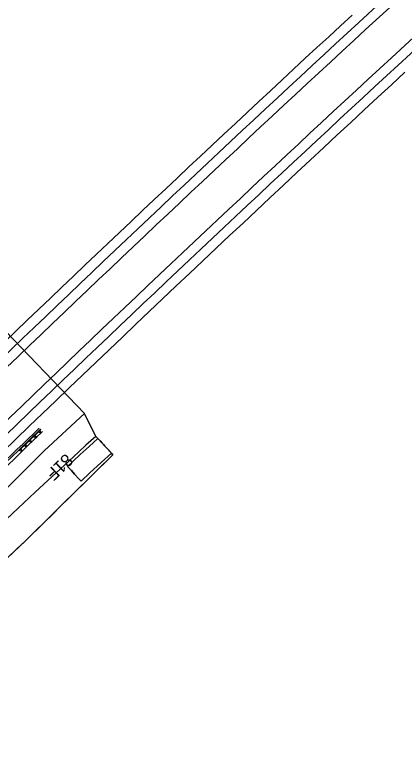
# Model space of a CAD drawing. Extents: x 2163396 to 2173129, y 605545 to 614595.
# Drawn here: x 2165051 to 2165523, y 606745 to 607658 of the extents above; entities that cross this region are included whole.
import ezdxf

# ---------------------------------------------------------------- set-up
doc = ezdxf.new("R2010")
doc.units = 0
for name, color, linetype in [('RD_PD_AsphRem', 7, 'Continuous'), ('RD_PD_CstnLmt', 7, 'Continuous'), ('RD_PD_EarthShd', 7, 'Continuous'), ('RD_PD_Final_LnLine', 7, 'Continuous'), ('RD_PD_Final_TrvlWay', 7, 'Continuous'), ('RD_PD_GR', 7, 'Continuous'), ('RD_PD_TX_CstnLmt', 7, 'Continuous')]:
    doc.layers.add(name, color=color, linetype=linetype)

msp = doc.modelspace()

# ---------------------------------------------------------------- linework, layer by layer
at = {"layer": 'RD_PD_AsphRem'}
for p, q in [((2165140.31, 607135.29), (2165129.58, 607125.43)), ((2165129.58, 607125.43), (2165121.02, 607117.6))]:
    msp.add_line(p, q, dxfattribs=at)
for points in [[(2165150.96, 607145.03), (2165148.58, 607147.57), (2165136.38, 607136.75), (2165127.82, 607128.91), (2165115.15, 607117.33), (2165095.54, 607099.04), (2165074.85, 607079.81), (2165054.3, 607060.49), (2165039.76, 607046.96)], [(2165167.33, 607127.18), (2165154.83, 607115.83), (2165141.22, 607103.26), (2165130.59, 607093.51), (2165128.03, 607096.12), (2165122.65, 607101.94), (2165118.85, 607106.07), (2165114.2, 607111.23), (2165121.02, 607117.6), (2165129.58, 607125.43), (2165140.31, 607135.29), (2165150.96, 607145.03)], [(2165159.26, 607135.87), (2165156.14, 607139.28), (2165150.96, 607145.03), (2165140.31, 607135.29)], [(2165154.83, 607115.83), (2165167.33, 607127.18), (2165160.79, 607134.21), (2165159.26, 607135.87)], [(2165041.44, 607000.41), (2165063.33, 607021.18), (2165086.71, 607044.04), (2165105.83, 607062.91), (2165126.11, 607083.08), (2165139.06, 607095.77), (2165148.75, 607105.57), (2165162.41, 607118.94), (2165168.97, 607125.36), (2165167.33, 607127.18)], [(2165121.02, 607117.6), (2165114.2, 607111.23), (2165118.85, 607106.07)], [(2165128.03, 607096.12), (2165130.59, 607093.51), (2165141.22, 607103.26), (2165154.83, 607115.83)], [(2165118.85, 607106.07), (2165122.65, 607101.94), (2165128.03, 607096.12)]]:
    msp.add_lwpolyline(points, dxfattribs=at)
at = {"layer": 'RD_PD_CstnLmt'}
for p, q in [((2165134.63, 607175.33), (2164996.96, 607318.65)), ((2165085.77, 607130.19), (2165134.63, 607175.33)), ((2165148.58, 607147.57), (2165134.63, 607175.33)), ((2165085.77, 607130.19), (2165015.33, 607059.57))]:
    msp.add_line(p, q, dxfattribs=at)
for points in [[(2165148.58, 607147.57), (2165150.96, 607145.03), (2165153.55, 607142.15), (2165156.14, 607139.28), (2165157.7, 607137.58), (2165159.26, 607135.87), (2165160.79, 607134.21), (2165164.06, 607130.7), (2165167.33, 607127.18), (2165168.15, 607126.27), (2165168.97, 607125.36)], [(2165168.97, 607125.36), (2165165.69, 607122.15), (2165162.41, 607118.94), (2165155.58, 607112.25), (2165148.75, 607105.57), (2165143.91, 607100.67), (2165139.06, 607095.77), (2165132.59, 607089.43), (2165126.11, 607083.08), (2165115.97, 607073), (2165105.83, 607062.91), (2165096.27, 607053.47), (2165086.71, 607044.04), (2165075.02, 607032.61), (2165063.33, 607021.18), (2165052.38, 607010.79), (2165041.44, 607000.41)]]:
    msp.add_lwpolyline(points, dxfattribs=at)
at = {"layer": 'RD_PD_EarthShd'}
msp.add_arc((2185842.87, 585582.73), 29937.08, 133.901337, 134.61799, dxfattribs=at)
at = {"layer": 'RD_PD_Final_LnLine'}
for p, q in [((2165466.73, 607649.08), (2167915.91, 609910.65)), ((2165474.87, 607640.27), (2167924.05, 609901.83)), ((2165506.31, 607606.23), (2167955.48, 609867.79)), ((2165514.45, 607597.41), (2167963.62, 609858.98))]:
    msp.add_line(p, q, dxfattribs=at)
for radius, end in [(30047.16, 135.071075), (30035.16, 135.071075), (30023.16, 135.071075), (29976.83, 135.071075), (29964.83, 135.071075), (29952.83, 134.085822)]:
    msp.add_arc((2185842.87, 585582.73), radius, 132.719474, end, dxfattribs=at)
at = {"layer": 'RD_PD_Final_TrvlWay'}
msp.add_arc((2185842.87, 585582.73), 29942.83, 133.901333, 134.468342, dxfattribs=at)
at = {"layer": 'RD_PD_GR'}
for p, q in [((2165081.34, 607156.15), (2165054.69, 607130.48)), ((2165055.04, 607130.12), (2165081.69, 607155.78)), ((2165079.15, 607153.34), (2165080.41, 607154.55)), ((2165080.41, 607154.55), (2165081.8, 607153.11)), ((2165081.69, 607155.78), (2165081.34, 607156.15)), ((2165073.39, 607147.79), (2165074.65, 607149)), ((2165074.78, 607146.35), (2165073.39, 607147.79)), ((2165074.65, 607149), (2165076.04, 607147.56)), ((2165076.04, 607147.56), (2165074.78, 607146.35)), ((2165075.41, 607146.96), (2165076.27, 607146.06)), ((2165075.64, 607145.45), (2165076.9, 607146.66)), ((2165080.54, 607151.9), (2165079.15, 607153.34)), ((2165081.8, 607153.11), (2165080.54, 607151.9)), ((2165081.17, 607152.51), (2165082.04, 607151.61)), ((2165081.41, 607151), (2165082.67, 607152.21)), ((2165061.86, 607136.69), (2165063.12, 607137.91)), ((2165063.25, 607135.25), (2165061.86, 607136.69)), ((2165063.12, 607137.91), (2165064.51, 607136.47)), ((2165064.51, 607136.47), (2165063.25, 607135.25)), ((2165063.88, 607135.86), (2165064.75, 607134.96)), ((2165067.63, 607142.24), (2165068.89, 607143.46)), ((2165069.01, 607140.8), (2165067.63, 607142.24)), ((2165068.89, 607143.46), (2165070.27, 607142.01)), ((2165070.27, 607142.01), (2165069.01, 607140.8)), ((2165069.64, 607141.41), (2165070.51, 607140.51)), ((2165069.88, 607139.9), (2165071.14, 607141.11)), ((2165054.69, 607130.48), (2165055.04, 607130.12)), ((2165056.1, 607131.14), (2165057.36, 607132.36)), ((2165057.49, 607129.7), (2165056.1, 607131.14)), ((2165057.36, 607132.36), (2165058.75, 607130.92)), ((2165058.75, 607130.92), (2165057.49, 607129.7)), ((2165058.12, 607130.31), (2165058.99, 607129.41)), ((2165058.36, 607128.8), (2165059.62, 607130.02)), ((2165059.61, 607134.52), (2165059.27, 607134.88)), ((2165064.12, 607134.35), (2165065.38, 607135.57))]:
    msp.add_line(p, q, dxfattribs=at)
msp.add_arc((2185842.87, 585582.73), 29940.83, 133.972137, 134.617988, dxfattribs=at)

# ---------------------------------------------------------------- texts
at = {"layer": 'RD_PD_TX_CstnLmt'}
msp.add_text('81F', height=15, rotation=223.92969, dxfattribs=at).set_placement((2165111.88, 607127.58))

doc.saveas('drawing.dxf')
